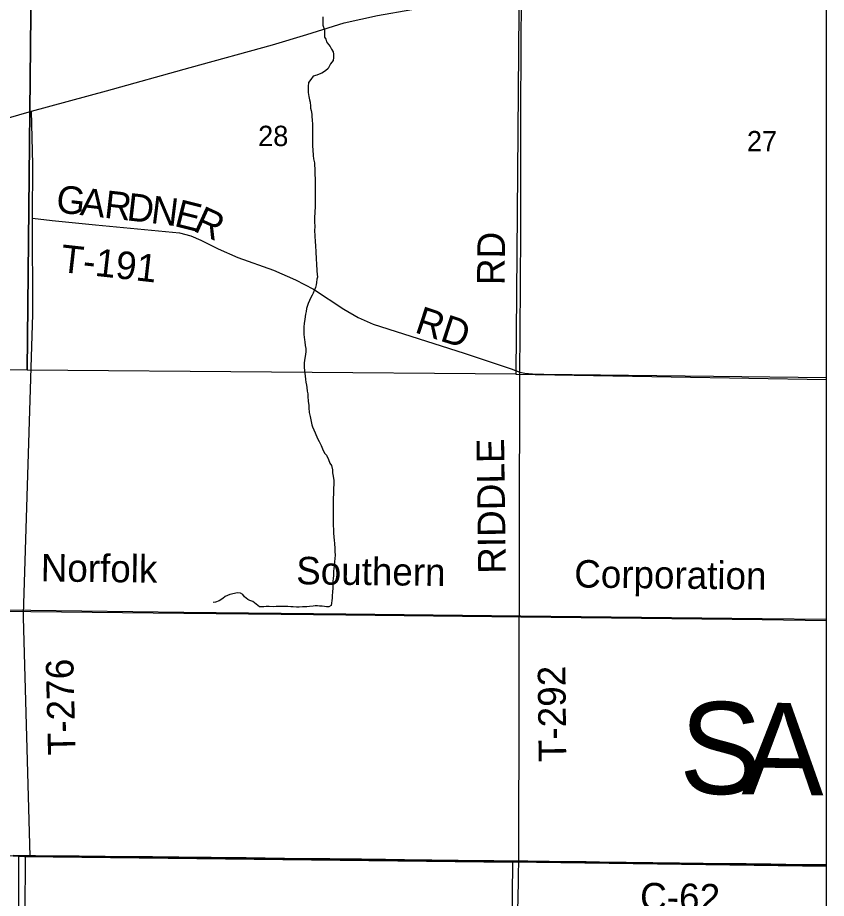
# Model space of a CAD drawing. Extents: x -8.5 to 18.7, y -20.3 to 7.
# Drawn here: x 15.411 to 18.741, y -11.043 to -7.416 of the extents above; entities that cross this region are included whole.
import ezdxf

# ---------------------------------------------------------------- set-up
doc = ezdxf.new("R2010")
doc.units = 0
for name, color, linetype in [('Default', 7, 'Continuous'), ('GM_X_Corporation', 7, 'Continuous'), ('GM_X_County_Road', 7, 'Continuous'), ('GM_X_County_Road_Text', 7, 'Continuous'), ('GM_X_County_Text', 7, 'Continuous'), ('GM_X_Minor_River', 7, 'Continuous'), ('GM_X_Rail_Line', 7, 'Continuous'), ('GM_X_Rail_Line_Text', 7, 'Continuous'), ('GM_X_Section', 7, 'Continuous'), ('GM_X_Section_Text', 7, 'Continuous'), ('GM_X_Township_Road', 7, 'Continuous'), ('GM_X_Township_Road_Text', 7, 'Continuous'), ('GM_X_Unincorporated_Text', 7, 'Continuous'), ('SH_Cut_Line', 7, 'Continuous')]:
    doc.layers.add(name, color=color, linetype=linetype)

msp = doc.modelspace()

# ---------------------------------------------------------------- linework, layer by layer
at = {"layer": 'Default'}
msp.add_lwpolyline([(18.7413, -8.906), (18.7413, -6.8969), (17.4795, -6.8884), (17.4623, -8.8834)], close=True, dxfattribs=at)
at = {"layer": 'GM_X_Corporation'}
for points in [[(15.3932, -10.8666), (15.4437, -10.867), (15.4631, -10.8672), (15.4852, -10.8673), (15.5735, -10.8685), (15.6642, -10.8693), (15.7724, -10.8705), (15.8557, -10.8713), (15.9663, -10.8718), (16.0745, -10.8731), (16.2087, -10.8746), (16.2982, -10.8756), (16.3517, -10.876), (16.5108, -10.8782), (16.6973, -10.8803), (16.8278, -10.8817), (16.926, -10.8832), (17.0043, -10.8846), (17.0578, -10.8849), (17.1175, -10.8857), (17.1709, -10.8861), (17.2256, -10.8872), (17.2953, -10.888), (17.3724, -10.8885), (17.4333, -10.8891), (17.4742, -10.8894), (17.5116, -10.8897), (17.6894, -10.892), (17.7516, -10.8922), (17.8075, -10.8934), (18.0263, -10.8957), (18.1369, -10.8973), (18.3321, -10.8998), (18.4117, -10.901), (18.4602, -10.9014), (18.5124, -10.9021), (18.5746, -10.9029), (18.7413, -10.9039), (18.7413, 1.1834)], [(18.7413, -20.262), (18.7413, -10.9039), (18.5746, -10.9029), (18.5124, -10.9021), (18.4602, -10.9014), (18.4117, -10.901), (18.3321, -10.8998), (18.1369, -10.8973), (18.0263, -10.8957), (17.8075, -10.8934), (17.7516, -10.8922), (17.6894, -10.892), (17.5116, -10.8897), (17.4742, -10.8894), (17.4333, -10.8891), (17.3724, -10.8885), (17.2953, -10.888), (17.2256, -10.8872), (17.1709, -10.8861), (17.1175, -10.8857), (17.0578, -10.8849), (17.0043, -10.8846), (16.926, -10.8832), (16.8278, -10.8817), (16.6973, -10.8803), (16.5108, -10.8782), (16.3517, -10.876), (16.2982, -10.8756), (16.2087, -10.8746), (16.0745, -10.8731), (15.9663, -10.8718), (15.8557, -10.8713), (15.7724, -10.8705), (15.6642, -10.8693), (15.5735, -10.8685), (15.4852, -10.8673), (15.4631, -10.8672), (15.4437, -10.867), (15.3932, -10.8666)]]:
    msp.add_lwpolyline(points, dxfattribs=at)
at = {"layer": 'GM_X_County_Road'}
msp.add_line((15.4442, -10.8681), (15.4636, -10.8683), dxfattribs=at)
for points in [[(14.4736, -8.218), (14.7523, -8.0784), (15.0039, -7.9529), (15.0371, -7.9379), (15.0816, -7.9192), (15.14, -7.8978), (15.1868, -7.882), (15.469, -7.8012), (15.7777, -7.7167), (16.1216, -7.621), (16.4603, -7.5284), (16.6028, -7.4859), (16.7559, -7.4377), (16.8934, -7.4072), (17.0345, -7.3824), (17.4857, -7.308), (17.7182, -7.2669), (18.0794, -7.208), (18.5689, -7.1263)], [(14.4489, -10.858), (14.5097, -10.8583), (14.6315, -10.8602), (14.7646, -10.8611), (14.859, -10.8623), (15.0393, -10.864), (15.1325, -10.8654), (15.2345, -10.8665), (15.3936, -10.8677), (15.4442, -10.8681)], [(15.4636, -10.8683), (15.4856, -10.8684), (15.5739, -10.8696), (15.6647, -10.8704), (15.7728, -10.8716), (15.8561, -10.8724), (15.9667, -10.8729), (16.0749, -10.8742), (16.2091, -10.8757), (16.2986, -10.8767), (16.3521, -10.8771), (16.5112, -10.8793), (16.6977, -10.8814), (16.8283, -10.8828), (16.9265, -10.8843), (17.0048, -10.8857), (17.0583, -10.886), (17.1179, -10.8868), (17.1714, -10.8872), (17.2261, -10.8883), (17.2957, -10.8891), (17.3728, -10.8896), (17.4337, -10.8902), (17.4746, -10.8905)], [(17.4746, -10.8905), (17.512, -10.8908), (17.6898, -10.8931), (17.752, -10.8933), (17.8079, -10.8945), (18.0267, -10.8968), (18.1374, -10.8984), (18.3326, -10.9009), (18.4121, -10.9021), (18.4606, -10.9025), (18.5128, -10.9032), (18.575, -10.904), (18.7413, -10.905)]]:
    msp.add_lwpolyline(points, dxfattribs=at)
at = {"layer": 'GM_X_Minor_River'}
for points in [[(16.6681, -7.4124), (16.6674, -7.4238), (16.6675, -7.4344), (16.6683, -7.4473), (16.6745, -7.4655), (16.6746, -7.4959), (16.6807, -7.505), (16.6831, -7.5149), (16.6907, -7.527), (16.6983, -7.5353), (16.7037, -7.5452), (16.7106, -7.5565), (16.7122, -7.5664), (16.7122, -7.5801), (16.7108, -7.5922), (16.7002, -7.606), (16.6957, -7.6143), (16.6897, -7.625), (16.6791, -7.6342), (16.664, -7.6441), (16.6526, -7.6487), (16.6428, -7.6526), (16.6276, -7.6572), (16.6186, -7.6709), (16.6095, -7.6831), (16.6081, -7.6991), (16.6074, -7.7082), (16.6074, -7.7242), (16.6106, -7.7409), (16.6137, -7.7538), (16.616, -7.7644), (16.6168, -7.7803), (16.6176, -7.7887), (16.62, -7.7986), (16.6223, -7.8137), (16.6224, -7.8229), (16.6239, -7.838), (16.6256, -7.8547), (16.626, -7.9452), (16.6268, -7.9603), (16.6285, -7.9839), (16.6301, -7.9968), (16.6332, -8.0143), (16.634, -8.0234), (16.6348, -8.0386), (16.6357, -8.0576), (16.6358, -8.0841), (16.6366, -8.0993), (16.6367, -8.1084), (16.6361, -8.135), (16.6369, -8.1502), (16.6362, -8.1647), (16.6371, -8.1814), (16.6363, -8.1897), (16.6364, -8.1989), (16.6357, -8.211), (16.635, -8.2201), (16.6343, -8.2376), (16.6336, -8.2513), (16.6337, -8.2597), (16.6345, -8.2726), (16.6338, -8.2954), (16.6354, -8.3113), (16.6355, -8.3204), (16.6363, -8.3341), (16.6372, -8.3599), (16.6388, -8.3759), (16.6388, -8.3858), (16.6405, -8.404), (16.6414, -8.4359), (16.643, -8.4518), (16.643, -8.4602), (16.6446, -8.4716), (16.6454, -8.4845), (16.6432, -8.4929), (16.6417, -8.5065), (16.6403, -8.5164), (16.638, -8.5271), (16.6328, -8.5392), (16.6283, -8.5499), (16.6245, -8.5583), (16.6185, -8.5682), (16.6125, -8.5804), (16.608, -8.5926), (16.6005, -8.6139)], [(16.6005, -8.6139), (16.5991, -8.6253), (16.5968, -8.6374), (16.5939, -8.658), (16.5917, -8.6754), (16.5895, -8.6884), (16.5897, -8.721), (16.592, -8.7423), (16.5944, -8.7514), (16.5952, -8.7666), (16.5975, -8.778), (16.5976, -8.7924), (16.5947, -8.8114), (16.5925, -8.8259), (16.5918, -8.8388), (16.5911, -8.8555), (16.5919, -8.8699), (16.5935, -8.8813), (16.5951, -8.8912), (16.5967, -8.9064), (16.5982, -8.917), (16.6006, -8.9299), (16.6021, -8.939), (16.6037, -8.9535), (16.6061, -8.9648), (16.6069, -8.9747), (16.6077, -8.9967), (16.6101, -9.0119), (16.6102, -9.0226), (16.6118, -9.0415), (16.6157, -9.059), (16.6227, -9.0932), (16.625, -9.1015), (16.6303, -9.1129), (16.6365, -9.1258), (16.6465, -9.1493), (16.6534, -9.1606), (16.6618, -9.1781), (16.6672, -9.1917), (16.6749, -9.2092), (16.6825, -9.2182), (16.6909, -9.2357), (16.6971, -9.2501), (16.7032, -9.2607), (16.7079, -9.2781), (16.7079, -9.2903), (16.7103, -9.304), (16.7134, -9.3214), (16.7135, -9.3351), (16.712, -9.3564), (16.7113, -9.3693), (16.7114, -9.3784), (16.71, -9.3928), (16.7102, -9.4521), (16.7111, -9.4635), (16.7111, -9.4719), (16.7112, -9.4909), (16.7114, -9.5395), (16.713, -9.5531), (16.7146, -9.5698), (16.7162, -9.5782), (16.7171, -9.604), (16.7179, -9.6139), (16.7187, -9.6291), (16.718, -9.6428), (16.7158, -9.6565), (16.7144, -9.6717), (16.7129, -9.6861), (16.7122, -9.6945), (16.7116, -9.7127), (16.7101, -9.7256), (16.7094, -9.7363), (16.7094, -9.7469), (16.7088, -9.7613), (16.7074, -9.7841), (16.7066, -9.7925), (16.7067, -9.8069), (16.7023, -9.8366), (16.6932, -9.8427), (16.6834, -9.8427), (16.675, -9.8413), (16.6651, -9.8398), (16.6545, -9.8391), (16.6461, -9.8384), (16.637, -9.8384), (16.6287, -9.8392), (16.6135, -9.8408), (16.6021, -9.8424), (16.5847, -9.8425), (16.571, -9.8433), (16.5596, -9.8433), (16.546, -9.8426), (16.5368, -9.8427), (16.5239, -9.8412), (16.5118, -9.8413), (16.4989, -9.8406), (16.4867, -9.8406), (16.4761, -9.8407), (16.4632, -9.8415), (16.4473, -9.8408), (16.4343, -9.8409)], [(16.4343, -9.8409), (16.4252, -9.8417), (16.4169, -9.8425), (16.4078, -9.8418), (16.3803, -9.8206), (16.3674, -9.8161), (16.359, -9.8116), (16.3461, -9.801), (16.3384, -9.792), (16.3293, -9.7859), (16.3149, -9.7845), (16.3043, -9.7876), (16.2853, -9.7907), (16.2664, -9.7999), (16.2565, -9.8075), (16.2414, -9.8175), (16.2262, -9.8229), (16.2164, -9.8244)]]:
    msp.add_lwpolyline(points, dxfattribs=at)
at = {"layer": 'GM_X_Rail_Line'}
for points in [[(12.89, -9.8312), (13.0368, -9.838), (13.7204, -9.8413), (14.4568, -9.8502), (15.1286, -9.8576), (15.4663, -9.8613), (16.0952, -9.8687), (16.7625, -9.8757), (17.4838, -9.8838), (18.4771, -9.8949), (18.7413, -9.8978)], [(12.89, -9.8312), (13.26, -9.8312), (13.7204, -9.8364), (14.4569, -9.8452), (15.1286, -9.8526), (15.4664, -9.8563), (16.0953, -9.8637), (16.7626, -9.8707), (17.4839, -9.8789), (18.4771, -9.89), (18.7413, -9.8928)]]:
    msp.add_lwpolyline(points, dxfattribs=at)
at = {"layer": 'GM_X_Section'}
for points in [[(13.4691, -6.8424), (15.4709, -6.8673), (15.4513, -8.8676), (13.4473, -8.8495)], [(15.4709, -6.8673), (17.4795, -6.8884), (17.4623, -8.8834), (15.4513, -8.8676)], [(15.4166, -10.8695), (15.4394, -10.8699), (17.4495, -10.8937), (17.4286, -12.923), (15.4216, -12.8944)]]:
    msp.add_lwpolyline(points, close=True, dxfattribs=at)
at = {"layer": 'GM_X_Township_Road'}
msp.add_line((17.4746, -10.8905), (17.4795, -8.8754), dxfattribs=at)
for points in [[(17.4795, -8.8754), (17.4811, -8.7159), (17.4839, -8.299), (17.4839, -7.7985), (17.4857, -7.308)], [(15.436, -9.8736), (15.4742, -8.6365), (15.4731, -8.2422), (15.4735, -8.0188), (15.469, -7.8012)], [(15.4731, -8.2422), (15.5532, -8.2507), (15.7322, -8.2685), (16.0782, -8.3019), (16.1249, -8.3139), (16.1654, -8.3324), (16.237, -8.3685), (16.3185, -8.4033), (16.4652, -8.4557), (16.5553, -8.4961), (16.6297, -8.5344), (16.7545, -8.6159), (16.8133, -8.6507), (16.875, -8.6776), (17.2493, -8.7978), (17.4432, -8.8621), (17.4795, -8.8754)], [(17.4795, -8.8754), (17.5001, -8.8804), (17.5309, -8.883), (17.5784, -8.8841), (18.7413, -8.8978)], [(15.4636, -10.8683), (15.4357, -9.8855), (15.436, -9.8736)], [(15.4297, -12.8859), (15.4298, -12.8794), (15.43, -12.8197), (15.4305, -12.7226), (15.433, -12.4717), (15.4343, -12.3948), (15.4343, -12.3097), (15.4342, -12.2456), (15.4354, -12.0601), (15.4361, -11.9456), (15.4369, -11.8421), (15.4381, -11.6993), (15.4393, -11.5181), (15.4415, -11.2131), (15.4425, -11.1165), (15.4427, -11.0431), (15.4435, -10.9338), (15.4444, -10.8817), (15.4443, -10.875), (15.4442, -10.8681)], [(17.4409, -12.9151), (17.441, -12.9094), (17.4428, -12.8222), (17.4434, -12.7562), (17.4456, -12.6718), (17.4487, -12.4965), (17.4527, -12.2802), (17.4522, -12.2415), (17.4537, -12.1957), (17.4547, -12.0871), (17.4562, -11.98), (17.4571, -11.9062), (17.4586, -11.7917), (17.4603, -11.6762), (17.4645, -11.4983), (17.4672, -11.333), (17.4701, -11.1573), (17.4736, -10.9743), (17.4739, -10.9356), (17.4745, -10.8982), (17.4746, -10.8905)]]:
    msp.add_lwpolyline(points, dxfattribs=at)
at = {"layer": 'GM_X_Unincorporated_Text'}
msp.add_lwpolyline([(18.7413, -12.9406), (18.7413, -10.9121), (17.4495, -10.8937), (17.4286, -12.923)], close=True, dxfattribs=at)
at = {"layer": 'SH_Cut_Line'}
for points in [[(15.3932, -10.8666), (15.4437, -10.867), (15.4631, -10.8672), (15.4852, -10.8673), (15.5735, -10.8685), (15.6642, -10.8693), (15.7724, -10.8705), (15.8557, -10.8713), (15.9663, -10.8718), (16.0745, -10.8731), (16.2087, -10.8746), (16.2982, -10.8756), (16.3517, -10.876), (16.5108, -10.8782), (16.6973, -10.8803), (16.8278, -10.8817), (16.926, -10.8832), (17.0043, -10.8846), (17.0578, -10.8849), (17.1175, -10.8857), (17.1709, -10.8861), (17.2256, -10.8872), (17.2953, -10.888), (17.3724, -10.8885), (17.4333, -10.8891), (17.4742, -10.8894), (17.5116, -10.8897), (17.6894, -10.892), (17.7516, -10.8922), (17.8075, -10.8934), (18.0263, -10.8957), (18.1369, -10.8973), (18.3321, -10.8998), (18.4117, -10.901), (18.4602, -10.9014), (18.5124, -10.9021), (18.5746, -10.9029), (18.7413, -10.9039), (18.7413, 6.938)], [(18.7413, -20.262), (18.7413, -10.9039), (18.5746, -10.9029), (18.5124, -10.9021), (18.4602, -10.9014), (18.4117, -10.901), (18.3321, -10.8998), (18.1369, -10.8973), (18.0263, -10.8957), (17.8075, -10.8934), (17.7516, -10.8922), (17.6894, -10.892), (17.5116, -10.8897), (17.4742, -10.8894), (17.4333, -10.8891), (17.3724, -10.8885), (17.2953, -10.888), (17.2256, -10.8872), (17.1709, -10.8861), (17.1175, -10.8857), (17.0578, -10.8849), (17.0043, -10.8846), (16.926, -10.8832), (16.8278, -10.8817), (16.6973, -10.8803), (16.5108, -10.8782), (16.3517, -10.876), (16.2982, -10.8756), (16.2087, -10.8746), (16.0745, -10.8731), (15.9663, -10.8718), (15.8557, -10.8713), (15.7724, -10.8705), (15.6642, -10.8693), (15.5735, -10.8685), (15.4852, -10.8673), (15.4631, -10.8672), (15.4437, -10.867), (15.3932, -10.8666)]]:
    msp.add_lwpolyline(points, dxfattribs=at)

# ---------------------------------------------------------------- texts
at = {"layer": 'GM_X_County_Road_Text'}
msp.add_text('C-62', height=0.11364, rotation=358.9703, dxfattribs=at).set_placement((17.9733, -11.0918))
at = {"layer": 'GM_X_County_Text'}
for s, rotation, p in [('S', 359.2121, (18.1343, -10.6105)), ('A', 359.2123, (18.3918, -10.614))]:
    msp.add_text(s, height=0.3788, rotation=rotation, dxfattribs=at).set_placement(p)
at = {"layer": 'GM_X_Rail_Line_Text'}
for s, height, rotation, p in [('Norfolk', 0.11326, 359.349, (15.5062, -9.7374)), ('Southern', 0.11326, 359.3031, (16.5579, -9.749)), ('Corporation', 0.113258, 359.3598, (17.7028, -9.7624))]:
    msp.add_text(s, height=height, rotation=rotation, dxfattribs=at).set_placement(p)
at = {"layer": 'GM_X_Section_Text'}
for s, p in [('28', (16.4015, -7.9447)), ('27', (18.414, -7.9663))]:
    msp.add_text(s, height=0.08371, rotation=0, dxfattribs=at).set_placement(p)
at = {"layer": 'GM_X_Township_Road_Text'}
for s, height, rotation, p in [('G', 0.1136, 353.5256, (15.5661, -8.217)), ('A', 0.1136, 353.5259, (15.6655, -8.2283)), ('R', 0.1136, 353.5253, (15.7648, -8.2395)), ('D', 0.1136, 353.5148, (15.8576, -8.2501)), ('N', 0.1136, 352.8691, (15.9566, -8.2613)), ('E', 0.1136, 345.8692, (16.0522, -8.273)), ('R', 0.1136, 335.509, (16.1295, -8.292)), ('RD', 0.11364, 89.5045, (17.4165, -8.5177)), ('T-191', 0.11364, 353.5975, (15.5841, -8.4626)), ('RD', 0.11364, 341.8777, (17.042, -8.7107)), ('RIDDLE', 0.11364, 90.7492, (17.4215, -9.7054)), ('T-276', 0.11364, 91.4043, (15.6503, -10.4516)), ('T-292', 0.11364, 90.5625, (17.6704, -10.4812))]:
    msp.add_text(s, height=height, rotation=rotation, dxfattribs=at).set_placement(p)

doc.saveas('drawing.dxf')
